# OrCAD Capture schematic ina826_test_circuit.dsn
size A; title: INA826 Precision, 200-µA Supply Current, 3-V to 36-V Supply; rev: 1.0; note: Datasheet: SBOS562G   EVM: SBOU115C
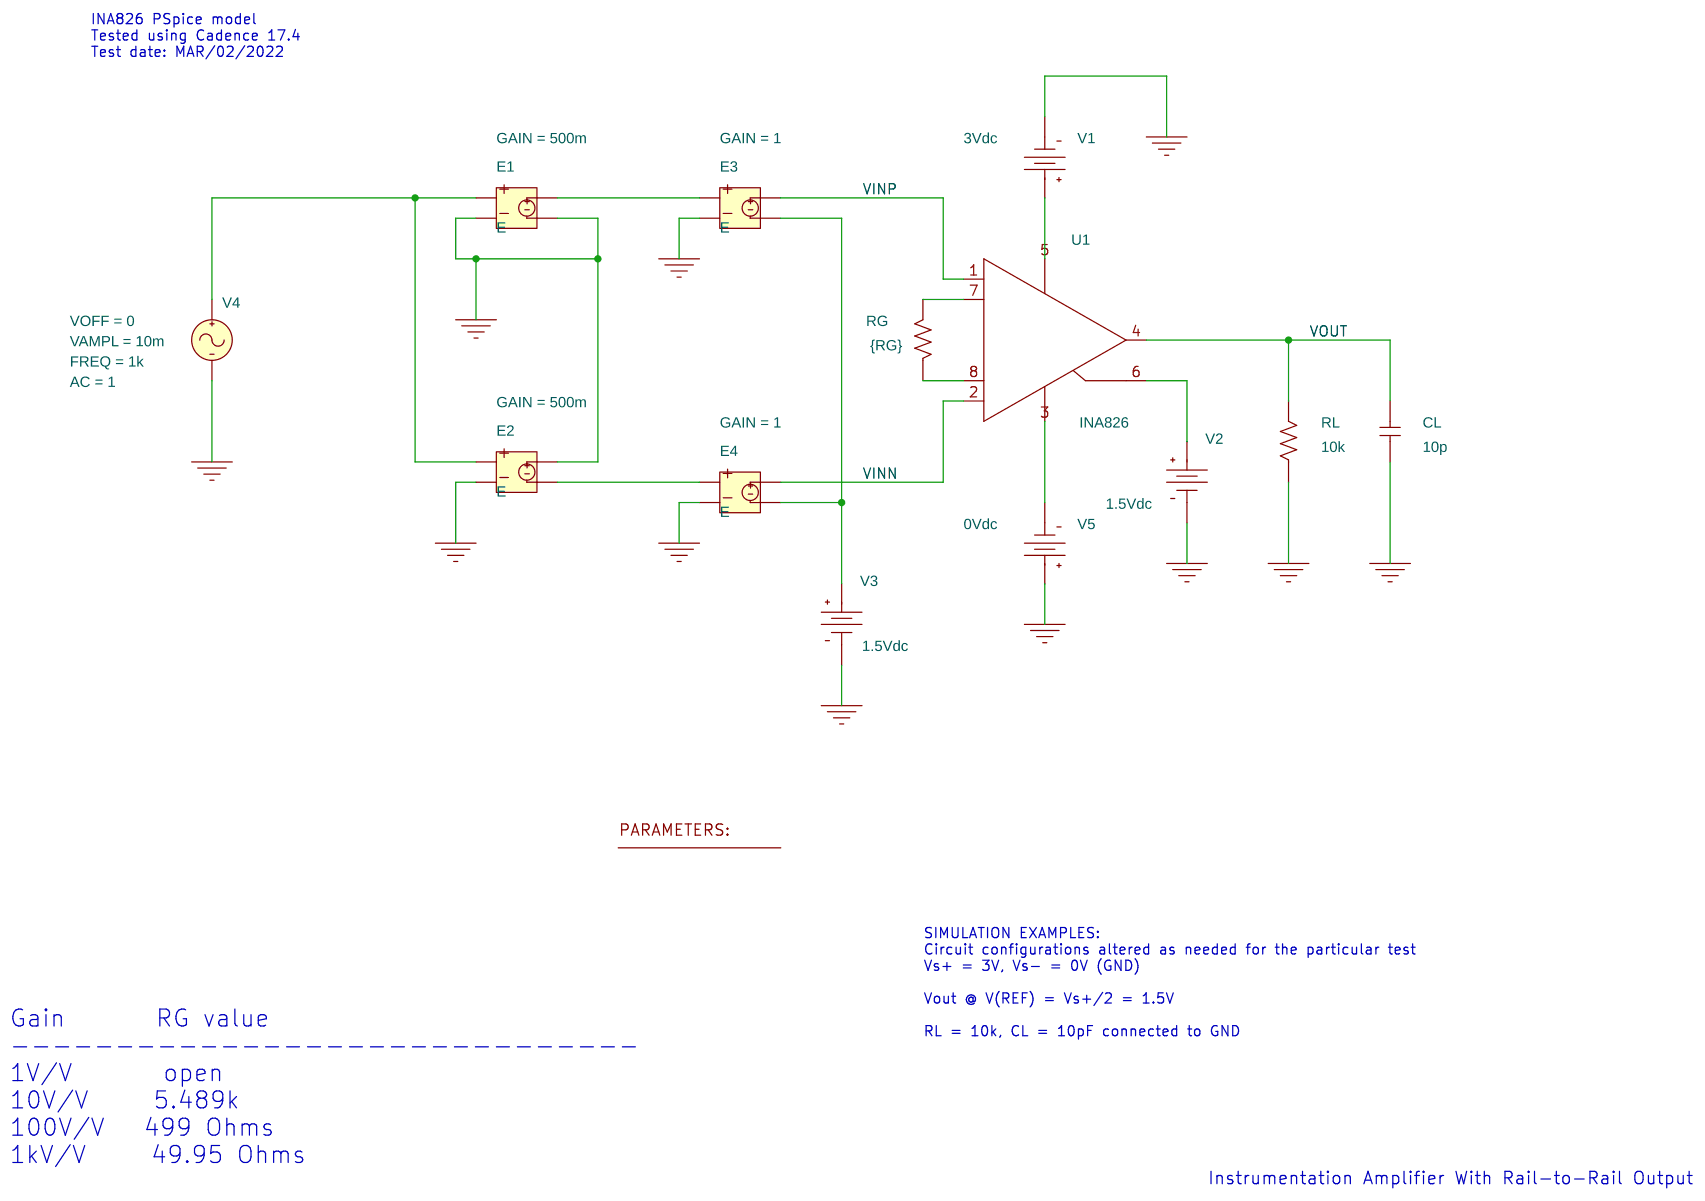
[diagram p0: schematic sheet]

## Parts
1  PARAM
CL  10p  [cap196]
E1  E
E2  E
E3  E
E4  E
RG  {RG}  [AXRC05]
RL  10k  [AXRC05]
U1  INA826
V1  VDC
V2  VDC
V3  VDC
V4  VSIN
V5  VDC

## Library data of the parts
1 = PARAM: RG: 499
CL = C
E1 E2 = E: GAIN: 500m
E3 E4 = E: GAIN: 1
RG RL = R
U1 = INA826
V1 = VDC: DC: 3Vdc
V2 V3 = VDC: DC: 1.5Vdc
V4 = VSIN: AC: 1; FREQ: 1k; VAMPL: 10m; VOFF: 0
V5 = VDC: DC: 0Vdc

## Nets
VINN: E4.3 U1.2(-)
VINP: E3.3 U1.1(+)
0: CL.1 E1.2 E1.4 E2.2 E2.3 E3.2 E4.2 RL.1 V1.1(-) V2.1(-) V3.1(-) V4.2(-) V5.0(+)
VOUT: CL.2 RL.2 U1.4(OUT)
N00135: U1.3(V-) V5.1(-)
N00172: RG.2 U1.7(RG+)
N00174: RG.1 U1.8(RG-)
N00361: U1.6(REF) V2.0(+)
N00444: U1.5(V+) V1.0(+)
N00637: E1.1 E2.1 V4.1(+)
N01493: E1.3 E3.1
N01546: E2.4 E4.1
N02405: E3.4 E4.4 V3.0(+)

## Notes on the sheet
- INA826 PSpice model
  Tested using Cadence 17.4
  Test date: MAR/02/2022
- SIMULATION EXAMPLES:
  Circuit configurations altered as needed for the particular test
  Vs+ = 3V, Vs- = 0V (GND)
  Vout @ V(REF) = Vs+/2 = 1.5V
  RL = 10k, CL = 10pF connected to GND
- Gain       RG value
  ------------------------------
  1V/V       open
  10V/V     5.489k
  100V/V   499 Ohms
  1kV/V     49.95 Ohms
- Instrumentation Amplifier With Rail-to-Rail Output
